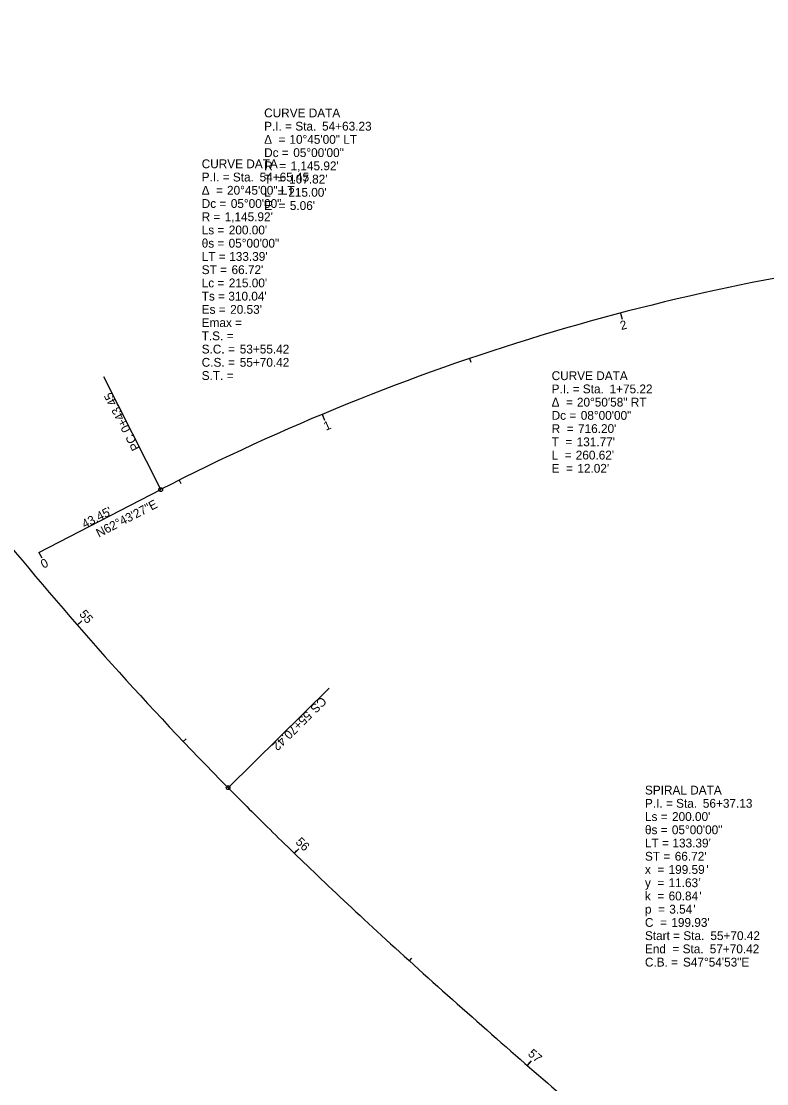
# Model space of a CAD drawing. Extents: x 1492452 to 1496782, y 514026 to 517659.
# Drawn here: x 1494542.5 to 1494779, y 514788.1 to 515125.3 of the extents above; entities that cross this region are included whole.
import ezdxf

# ---------------------------------------------------------------- set-up
doc = ezdxf.new("R2010")
doc.units = 0
for name, color, linetype in [('BR_X_SV_Abut', 7, 'Continuous'), ('Default', 7, 'Continuous'), ('DR_X_Ditch', 7, 'Continuous'), ('DR_X_Elev_Flow', 7, 'Continuous'), ('DT_X_Break_Line', 7, 'Continuous'), ('DT_X_Contour_Minor', 7, 'Continuous'), ('DT_X_Island', 7, 'Continuous'), ('DT_X_TIN_Hull', 7, 'Continuous'), ('DT_X_Triangles', 7, 'Continuous'), ('DT_X_Void', 7, 'Continuous'), ('GE_X_Cells', 7, 'Continuous'), ('PV_X_COP', 7, 'Continuous'), ('PV_X_EOP', 7, 'Continuous'), ('PV_X_Shoulder_Aggregate', 7, 'Continuous'), ('RD_X_Cells', 7, 'Continuous'), ('RD_X_GR_Lt', 7, 'Continuous'), ('RD_X_GR_Rt', 7, 'Continuous'), ('RD_X_Wall', 7, 'Continuous'), ('SN_X_Public', 7, 'Continuous'), ('SV_X_Random_Point', 7, 'Continuous'), ('SV_X_Top_of_Bank', 7, 'Continuous'), ('UT_X_Electric_Cells', 7, 'Continuous'), ('UT_X_Misc_Cells', 7, 'Continuous'), ('UT_X_Water', 7, 'Continuous'), ('UT_X_Water_Cells', 7, 'Continuous'), ('VG_X_Cells', 7, 'Continuous'), ('XS_X_Ground_Line', 7, 'Continuous')]:
    doc.layers.add(name, color=color, linetype=linetype)

msp = doc.modelspace()

# ---------------------------------------------------------------- linework, layer by layer
at = {"layer": 'Default'}
msp.add_line((1494548.11, 514956.7), (1494586.73, 514976.61), dxfattribs=at)
for centre, radius, start, end in [((1486425.91, 524780.42), 12277.67, 302.444021, 313.600151), ((1494914.94, 514340.04), 716.2, 96.42645, 117.27596)]:
    msp.add_arc(centre, radius, start, end, dxfattribs=at)
at = {"layer": 'DT_X_Contour_Minor'}
msp.add_line((1494560.25, 514933.64), (1494561.16, 514934.43), dxfattribs=at)
at = {"layer": 'DT_X_TIN_Hull'}
for p, q in [((1494732.57, 515032.63), (1494733.08, 515030.7)), ((1494684.7, 515018.23), (1494685.09, 515017.09)), ((1494637.96, 515000.51), (1494638.73, 514998.67)), ((1494592.56, 514979.58), (1494593.1, 514978.51)), ((1494548.11, 514956.7), (1494549.02, 514954.92))]:
    msp.add_line(p, q, dxfattribs=at)
at = {"layer": 'DT_X_Void'}
msp.add_line((1494586.73, 514976.61), (1494568.72, 515012.45), dxfattribs=at)
msp.add_circle((1494586.73, 514976.61), 0.6, dxfattribs=at)
at = {"layer": 'GE_X_Cells'}
msp.add_line((1494548.11, 514956.7), (1494586.73, 514976.61), dxfattribs=at)
for centre, radius, start, end in [((1486425.91, 524780.42), 12277.67, 302.444021, 313.600151), ((1494914.94, 514340.04), 716.2, 96.42645, 117.27596)]:
    msp.add_arc(centre, radius, start, end, dxfattribs=at)
at = {"layer": 'PV_X_EOP'}
msp.add_line((1494608.11, 514882), (1494640.16, 514913.59), dxfattribs=at)
msp.add_circle((1494608.11, 514882), 0.6, dxfattribs=at)
at = {"layer": 'PV_X_Shoulder_Aggregate'}
for p, q in [((1494560.25, 514933.64), (1494561.76, 514934.96)), ((1494593.91, 514896.67), (1494594.78, 514897.5)), ((1494629.13, 514861.19), (1494630.52, 514862.62)), ((1494665.64, 514827.03), (1494666.45, 514827.92)), ((1494703.04, 514793.85), (1494704.36, 514795.36))]:
    msp.add_line(p, q, dxfattribs=at)
at = {"layer": 'RD_X_Cells'}
msp.add_line((1494586.73, 514976.61), (1494568.72, 515012.45), dxfattribs=at)
msp.add_circle((1494586.73, 514976.61), 0.6, dxfattribs=at)
at = {"layer": 'RD_X_GR_Rt'}
msp.add_line((1494608.11, 514882), (1494640.16, 514913.59), dxfattribs=at)
msp.add_circle((1494608.11, 514882), 0.6, dxfattribs=at)
at = {"layer": 'RD_X_Wall'}
for p, q in [((1494560.25, 514933.64), (1494561.76, 514934.96)), ((1494629.13, 514861.19), (1494629.97, 514862.05)), ((1494703.04, 514793.85), (1494703.83, 514794.75))]:
    msp.add_line(p, q, dxfattribs=at)
at = {"layer": 'SV_X_Top_of_Bank'}
msp.add_arc((1495424.3, 515686.35), 1145.92, 213.83122, 224.58118, dxfattribs=at)
msp.add_arc((1495424.3, 515686.35), 1145.92, 213.83122, 224.58118, dxfattribs=at)
msp.add_open_spline([(1494608.11, 514882), (1494612.01, 514878.04), (1494619.86, 514870.19), (1494635.79, 514854.68), (1494656.04, 514835.67), (1494680.78, 514813.33), (1494705.84, 514791.35), (1494726.9, 514773.23), (1494743.8, 514758.81), (1494752.26, 514751.6), (1494756.49, 514748)], degree=3, dxfattribs=at)
msp.add_open_spline([(1494608.11, 514882), (1494612.01, 514878.04), (1494619.86, 514870.19), (1494635.79, 514854.68), (1494656.04, 514835.67), (1494680.78, 514813.33), (1494705.84, 514791.35), (1494726.9, 514773.23), (1494743.8, 514758.81), (1494752.26, 514751.6), (1494756.49, 514748)], degree=3, dxfattribs=at)
at = {"layer": 'UT_X_Misc_Cells'}
msp.add_line((1494586.73, 514976.61), (1494568.72, 515012.45), dxfattribs=at)
msp.add_circle((1494586.73, 514976.61), 0.6, dxfattribs=at)
at = {"layer": 'UT_X_Water_Cells'}
for p, q in [((1494732.57, 515032.63), (1494732.88, 515031.47)), ((1494637.96, 515000.51), (1494638.42, 514999.41)), ((1494548.11, 514956.7), (1494549.02, 514954.92))]:
    msp.add_line(p, q, dxfattribs=at)
at = {"layer": 'VG_X_Cells'}
msp.add_line((1494548.11, 514956.7), (1494549.02, 514954.92), dxfattribs=at)
at = {"layer": 'XS_X_Ground_Line'}
msp.add_line((1494608.11, 514882), (1494640.16, 514913.59), dxfattribs=at)
msp.add_circle((1494608.11, 514882), 0.6, dxfattribs=at)

# ---------------------------------------------------------------- texts
at = {"layer": 'BR_X_SV_Abut'}
for s, p in [('CURVE DATA', (1494619.55, 515094.76)), ('P.I. = Sta. ', (1494619.55, 515090.56)), ('54+63.23', (1494637.92, 515090.56)), ('Δ  = ', (1494619.55, 515086.36)), ('10°45\'00" LT', (1494627.57, 515086.36)), ('Dc = ', (1494619.55, 515082.16)), ('05°00\'00"', (1494628.79, 515082.16)), ('CURVE DATA', (1494599.74, 515078.61)), ('R  = ', (1494619.55, 515077.96)), ("1,145.92'", (1494627.92, 515077.96)), ('P.I. = Sta. ', (1494599.74, 515074.41)), ('54+65.45', (1494618.11, 515074.41)), ('T  = ', (1494619.55, 515073.76)), ("107.82'", (1494627.48, 515073.76)), ('Δ  = ', (1494599.74, 515070.21)), ('20°45\'00" LT', (1494607.77, 515070.21)), ('L  = ', (1494619.55, 515069.56)), ("215.00'", (1494627.2, 515069.56)), ('Dc = ', (1494599.74, 515066.01)), ('05°00\'00"', (1494608.98, 515066.01)), ('E  = ', (1494619.55, 515065.36)), ("5.06'", (1494627.7, 515065.36)), ('R = ', (1494599.74, 515061.81)), ("1,145.92'", (1494607.02, 515061.81)), ('Ls = ', (1494599.74, 515057.61)), ("200.00'", (1494608.33, 515057.61)), ('θs = ', (1494599.74, 515053.41)), ('05°00\'00"', (1494608.28, 515053.41)), ('LT = ', (1494599.74, 515049.21)), ("133.39'", (1494608.47, 515049.21)), ('ST = ', (1494599.74, 515045.01)), ("66.72'", (1494609.2, 515045.01)), ('Lc = ', (1494599.74, 515040.81)), ("215.00'", (1494608.33, 515040.81)), ('Ts = ', (1494599.74, 515036.61)), ("310.04'", (1494608.19, 515036.61)), ('Es = ', (1494599.74, 515032.41)), ("20.53'", (1494608.77, 515032.41)), ('Emax = ', (1494599.74, 515028.21)), ('T.S. = ', (1494599.74, 515024.01)), ('S.C. = ', (1494599.74, 515019.81)), ('53+55.42', (1494611.81, 515019.81)), ('C.S. = ', (1494599.74, 515015.61)), ('55+70.42', (1494611.81, 515015.61)), ('S.T. = ', (1494599.74, 515011.41)), ('SPIRAL DATA', (1494740.35, 514879.85)), ('P.I. = Sta. ', (1494740.35, 514875.65)), ('56+37.13', (1494758.72, 514875.65)), ('Ls = ', (1494740.35, 514871.45)), ("200.00'", (1494748.94, 514871.45)), ('θs = ', (1494740.35, 514867.25)), ('05°00\'00"', (1494748.89, 514867.25)), ('LT = ', (1494740.35, 514863.05)), ("133.39'", (1494749.08, 514863.05)), ('ST = ', (1494740.35, 514858.85)), ("66.72'", (1494749.81, 514858.85)), ('199.59', (1494747.85, 514854.65)), ("'", (1494759.81, 514854.65)), ('x  = ', (1494740.35, 514854.65)), ('y  = ', (1494740.35, 514850.45)), ('11.63', (1494747.85, 514850.45)), ("'", (1494757.35, 514850.45)), ('k  = ', (1494740.35, 514846.25)), ('60.84', (1494747.85, 514846.25)), ("'", (1494757.64, 514846.25)), ('p  = ', (1494740.35, 514842.05)), ('3.54', (1494748.07, 514842.05)), ("'", (1494755.68, 514842.05)), ('C  = ', (1494740.35, 514837.85)), ("199.93'", (1494748.72, 514837.85)), ('Start = Sta. ', (1494740.35, 514833.65)), ('55+70.42', (1494761.11, 514833.65)), ('End  = Sta. ', (1494740.35, 514829.45)), ('57+70.42', (1494760.9, 514829.45)), ('C.B. = ', (1494740.35, 514825.25)), ('S47°54\'53"E', (1494752.42, 514825.25))]:
    msp.add_text(s, height=2.8, dxfattribs=at).set_placement(p)
at = {"layer": 'DR_X_Ditch'}
msp.add_text("43.45'", height=2.8, rotation=27.276, dxfattribs=at).set_placement((1494562.6, 514964.22))
at = {"layer": 'DR_X_Elev_Flow'}
for s, p in [('CURVE DATA', (1494710.75, 515011.37)), ('P.I. = Sta. ', (1494710.75, 515007.17)), ('1+75.22', (1494729.12, 515007.17)), ('Δ  = ', (1494710.75, 515002.97)), ('20°50\'58" RT', (1494718.77, 515002.97)), ('Dc = ', (1494710.75, 514998.77)), ('08°00\'00"', (1494719.99, 514998.77)), ('R  = ', (1494710.75, 514994.57)), ("716.20'", (1494719.12, 514994.57)), ('T  = ', (1494710.75, 514990.37)), ("131.77'", (1494718.69, 514990.37)), ('L  = ', (1494710.75, 514986.17)), ("260.62'", (1494718.4, 514986.17)), ('E  = ', (1494710.75, 514981.97)), ("12.02'", (1494718.91, 514981.97))]:
    msp.add_text(s, height=2.8, dxfattribs=at).set_placement(p)
at = {"layer": 'DT_X_Break_Line'}
msp.add_text('N62°43\'27"E', height=2.8, rotation=27.276, dxfattribs=at).set_placement((1494567.12, 514961.35))
at = {"layer": 'DT_X_Island'}
for s, p in [('CURVE DATA', (1494710.75, 515011.37)), ('P.I. = Sta. ', (1494710.75, 515007.17)), ('1+75.22', (1494729.12, 515007.17)), ('Δ  = ', (1494710.75, 515002.97)), ('20°50\'58" RT', (1494718.77, 515002.97)), ('Dc = ', (1494710.75, 514998.77)), ('08°00\'00"', (1494719.99, 514998.77)), ('R  = ', (1494710.75, 514994.57)), ("716.20'", (1494719.12, 514994.57)), ('T  = ', (1494710.75, 514990.37)), ("131.77'", (1494718.69, 514990.37)), ('L  = ', (1494710.75, 514986.17)), ("260.62'", (1494718.4, 514986.17)), ('E  = ', (1494710.75, 514981.97)), ("12.02'", (1494718.91, 514981.97))]:
    msp.add_text(s, height=2.8, dxfattribs=at).set_placement(p)
at = {"layer": 'DT_X_TIN_Hull'}
for s, rotation, p in [('2', 14.752, (1494732.86, 515027.23)), ('1', 22.752, (1494639.14, 514995.26)), ('0', 27.276, (1494549.55, 514951.48))]:
    msp.add_text(s, height=2.8, rotation=rotation, dxfattribs=at).set_placement(p)
at = {"layer": 'DT_X_Triangles'}
for s, p in [('CURVE DATA', (1494619.55, 515094.76)), ('P.I. = Sta. ', (1494619.55, 515090.56)), ('54+63.23', (1494637.92, 515090.56)), ('Δ  = ', (1494619.55, 515086.36)), ('10°45\'00" LT', (1494627.57, 515086.36)), ('Dc = ', (1494619.55, 515082.16)), ('05°00\'00"', (1494628.79, 515082.16)), ('CURVE DATA', (1494599.74, 515078.61)), ('R  = ', (1494619.55, 515077.96)), ("1,145.92'", (1494627.92, 515077.96)), ('P.I. = Sta. ', (1494599.74, 515074.41)), ('54+65.45', (1494618.11, 515074.41)), ('T  = ', (1494619.55, 515073.76)), ("107.82'", (1494627.48, 515073.76)), ('Δ  = ', (1494599.74, 515070.21)), ('20°45\'00" LT', (1494607.77, 515070.21)), ('L  = ', (1494619.55, 515069.56)), ("215.00'", (1494627.2, 515069.56)), ('Dc = ', (1494599.74, 515066.01)), ('05°00\'00"', (1494608.98, 515066.01)), ('E  = ', (1494619.55, 515065.36)), ("5.06'", (1494627.7, 515065.36)), ('R = ', (1494599.74, 515061.81)), ("1,145.92'", (1494607.02, 515061.81)), ('Ls = ', (1494599.74, 515057.61)), ("200.00'", (1494608.33, 515057.61)), ('θs = ', (1494599.74, 515053.41)), ('05°00\'00"', (1494608.28, 515053.41)), ('LT = ', (1494599.74, 515049.21)), ("133.39'", (1494608.47, 515049.21)), ('ST = ', (1494599.74, 515045.01)), ("66.72'", (1494609.2, 515045.01)), ('Lc = ', (1494599.74, 515040.81)), ("215.00'", (1494608.33, 515040.81)), ('Ts = ', (1494599.74, 515036.61)), ("310.04'", (1494608.19, 515036.61)), ('Es = ', (1494599.74, 515032.41)), ("20.53'", (1494608.77, 515032.41)), ('Emax = ', (1494599.74, 515028.21)), ('T.S. = ', (1494599.74, 515024.01)), ('S.C. = ', (1494599.74, 515019.81)), ('53+55.42', (1494611.81, 515019.81)), ('C.S. = ', (1494599.74, 515015.61)), ('55+70.42', (1494611.81, 515015.61)), ('S.T. = ', (1494599.74, 515011.41)), ('SPIRAL DATA', (1494740.35, 514879.85)), ('P.I. = Sta. ', (1494740.35, 514875.65)), ('56+37.13', (1494758.72, 514875.65)), ('Ls = ', (1494740.35, 514871.45)), ("200.00'", (1494748.94, 514871.45)), ('θs = ', (1494740.35, 514867.25)), ('05°00\'00"', (1494748.89, 514867.25)), ('LT = ', (1494740.35, 514863.05)), ("133.39'", (1494749.08, 514863.05)), ('ST = ', (1494740.35, 514858.85)), ("66.72'", (1494749.81, 514858.85)), ('199.59', (1494747.85, 514854.65)), ("'", (1494759.81, 514854.65)), ('x  = ', (1494740.35, 514854.65)), ('y  = ', (1494740.35, 514850.45)), ('11.63', (1494747.85, 514850.45)), ("'", (1494757.35, 514850.45)), ('k  = ', (1494740.35, 514846.25)), ('60.84', (1494747.85, 514846.25)), ("'", (1494757.64, 514846.25)), ('p  = ', (1494740.35, 514842.05)), ('3.54', (1494748.07, 514842.05)), ("'", (1494755.68, 514842.05)), ('C  = ', (1494740.35, 514837.85)), ("199.93'", (1494748.72, 514837.85)), ('Start = Sta. ', (1494740.35, 514833.65)), ('55+70.42', (1494761.11, 514833.65)), ('End  = Sta. ', (1494740.35, 514829.45)), ('57+70.42', (1494760.9, 514829.45)), ('C.B. = ', (1494740.35, 514825.25)), ('S47°54\'53"E', (1494752.42, 514825.25))]:
    msp.add_text(s, height=2.8, dxfattribs=at).set_placement(p)
at = {"layer": 'DT_X_Void'}
for s, p in [('0+43.45', (1494577.34, 514995.64)), ('PC', (1494580.32, 514989.84))]:
    msp.add_text(s, height=2.8, rotation=117.276, dxfattribs=at).set_placement(p)
at = {"layer": 'PV_X_COP'}
for s, p in [('CURVE DATA', (1494619.55, 515094.76)), ('P.I. = Sta. ', (1494619.55, 515090.56)), ('54+63.23', (1494637.92, 515090.56)), ('Δ  = ', (1494619.55, 515086.36)), ('10°45\'00" LT', (1494627.57, 515086.36)), ('Dc = ', (1494619.55, 515082.16)), ('05°00\'00"', (1494628.79, 515082.16)), ('CURVE DATA', (1494599.74, 515078.61)), ('R  = ', (1494619.55, 515077.96)), ("1,145.92'", (1494627.92, 515077.96)), ('P.I. = Sta. ', (1494599.74, 515074.41)), ('54+65.45', (1494618.11, 515074.41)), ('T  = ', (1494619.55, 515073.76)), ("107.82'", (1494627.48, 515073.76)), ('Δ  = ', (1494599.74, 515070.21)), ('20°45\'00" LT', (1494607.77, 515070.21)), ('L  = ', (1494619.55, 515069.56)), ("215.00'", (1494627.2, 515069.56)), ('Dc = ', (1494599.74, 515066.01)), ('05°00\'00"', (1494608.98, 515066.01)), ('E  = ', (1494619.55, 515065.36)), ("5.06'", (1494627.7, 515065.36)), ('R = ', (1494599.74, 515061.81)), ("1,145.92'", (1494607.02, 515061.81)), ('Ls = ', (1494599.74, 515057.61)), ("200.00'", (1494608.33, 515057.61)), ('θs = ', (1494599.74, 515053.41)), ('05°00\'00"', (1494608.28, 515053.41)), ('LT = ', (1494599.74, 515049.21)), ("133.39'", (1494608.47, 515049.21)), ('ST = ', (1494599.74, 515045.01)), ("66.72'", (1494609.2, 515045.01)), ('Lc = ', (1494599.74, 515040.81)), ("215.00'", (1494608.33, 515040.81)), ('Ts = ', (1494599.74, 515036.61)), ("310.04'", (1494608.19, 515036.61)), ('Es = ', (1494599.74, 515032.41)), ("20.53'", (1494608.77, 515032.41)), ('Emax = ', (1494599.74, 515028.21)), ('T.S. = ', (1494599.74, 515024.01)), ('S.C. = ', (1494599.74, 515019.81)), ('53+55.42', (1494611.81, 515019.81)), ('C.S. = ', (1494599.74, 515015.61)), ('55+70.42', (1494611.81, 515015.61)), ('S.T. = ', (1494599.74, 515011.41)), ('SPIRAL DATA', (1494740.35, 514879.85)), ('P.I. = Sta. ', (1494740.35, 514875.65)), ('56+37.13', (1494758.72, 514875.65)), ('Ls = ', (1494740.35, 514871.45)), ("200.00'", (1494748.94, 514871.45)), ('θs = ', (1494740.35, 514867.25)), ('05°00\'00"', (1494748.89, 514867.25)), ('LT = ', (1494740.35, 514863.05)), ("133.39'", (1494749.08, 514863.05)), ('ST = ', (1494740.35, 514858.85)), ("66.72'", (1494749.81, 514858.85)), ('199.59', (1494747.85, 514854.65)), ("'", (1494759.81, 514854.65)), ('x  = ', (1494740.35, 514854.65)), ('y  = ', (1494740.35, 514850.45)), ('11.63', (1494747.85, 514850.45)), ("'", (1494757.35, 514850.45)), ('k  = ', (1494740.35, 514846.25)), ('60.84', (1494747.85, 514846.25)), ("'", (1494757.64, 514846.25)), ('p  = ', (1494740.35, 514842.05)), ('3.54', (1494748.07, 514842.05)), ("'", (1494755.68, 514842.05)), ('C  = ', (1494740.35, 514837.85)), ("199.93'", (1494748.72, 514837.85)), ('Start = Sta. ', (1494740.35, 514833.65)), ('55+70.42', (1494761.11, 514833.65)), ('End  = Sta. ', (1494740.35, 514829.45)), ('57+70.42', (1494760.9, 514829.45)), ('C.B. = ', (1494740.35, 514825.25)), ('S47°54\'53"E', (1494752.42, 514825.25))]:
    msp.add_text(s, height=2.8, dxfattribs=at).set_placement(p)
at = {"layer": 'PV_X_EOP'}
for s, p in [('CS', (1494637.69, 514911.09)), ('55+70.42', (1494633.04, 514906.51))]:
    msp.add_text(s, height=2.8, rotation=224.5812, dxfattribs=at).set_placement(p)
at = {"layer": 'PV_X_Shoulder_Aggregate'}
for s, rotation, p in [('55', 311.0604, (1494560.73, 514936.98)), ('56', 315.951, (1494629.32, 514864.54)), ('57', 318.9614, (1494703.02, 514797.25))]:
    msp.add_text(s, height=2.8, rotation=rotation, dxfattribs=at).set_placement(p)
at = {"layer": 'RD_X_Cells'}
for s, p in [('0+43.45', (1494577.34, 514995.64)), ('PC', (1494580.32, 514989.84))]:
    msp.add_text(s, height=2.8, rotation=117.276, dxfattribs=at).set_placement(p)
at = {"layer": 'RD_X_GR_Lt'}
msp.add_text("43.45'", height=2.8, rotation=27.276, dxfattribs=at).set_placement((1494562.6, 514964.22))
at = {"layer": 'RD_X_GR_Rt'}
for s, p in [('CS', (1494637.69, 514911.09)), ('55+70.42', (1494633.04, 514906.51))]:
    msp.add_text(s, height=2.8, rotation=224.5812, dxfattribs=at).set_placement(p)
at = {"layer": 'RD_X_Wall'}
msp.add_text('55', height=2.8, rotation=311.0604, dxfattribs=at).set_placement((1494560.73, 514936.98))
at = {"layer": 'SN_X_Public'}
for s, p in [('CURVE DATA', (1494710.75, 515011.37)), ('P.I. = Sta. ', (1494710.75, 515007.17)), ('1+75.22', (1494729.12, 515007.17)), ('Δ  = ', (1494710.75, 515002.97)), ('20°50\'58" RT', (1494718.77, 515002.97)), ('Dc = ', (1494710.75, 514998.77)), ('08°00\'00"', (1494719.99, 514998.77)), ('R  = ', (1494710.75, 514994.57)), ("716.20'", (1494719.12, 514994.57)), ('T  = ', (1494710.75, 514990.37)), ("131.77'", (1494718.69, 514990.37)), ('L  = ', (1494710.75, 514986.17)), ("260.62'", (1494718.4, 514986.17)), ('E  = ', (1494710.75, 514981.97)), ("12.02'", (1494718.91, 514981.97))]:
    msp.add_text(s, height=2.8, dxfattribs=at).set_placement(p)
at = {"layer": 'SV_X_Random_Point'}
msp.add_text('N62°43\'27"E', height=2.8, rotation=27.276, dxfattribs=at).set_placement((1494567.12, 514961.35))
at = {"layer": 'UT_X_Electric_Cells'}
msp.add_text('N62°43\'27"E', height=2.8, rotation=27.276, dxfattribs=at).set_placement((1494567.12, 514961.35))
at = {"layer": 'UT_X_Misc_Cells'}
for s, p in [('0+43.45', (1494577.34, 514995.64)), ('PC', (1494580.32, 514989.84))]:
    msp.add_text(s, height=2.8, rotation=117.276, dxfattribs=at).set_placement(p)
at = {"layer": 'UT_X_Water'}
msp.add_text("43.45'", height=2.8, rotation=27.276, dxfattribs=at).set_placement((1494562.6, 514964.22))
at = {"layer": 'UT_X_Water_Cells'}
msp.add_text('0', height=2.8, rotation=27.276, dxfattribs=at).set_placement((1494549.55, 514951.48))
at = {"layer": 'VG_X_Cells'}
msp.add_text('0', height=2.8, rotation=27.276, dxfattribs=at).set_placement((1494549.55, 514951.48))
at = {"layer": 'XS_X_Ground_Line'}
for s, p in [('CS', (1494637.69, 514911.09)), ('55+70.42', (1494633.04, 514906.51))]:
    msp.add_text(s, height=2.8, rotation=224.5812, dxfattribs=at).set_placement(p)

doc.saveas('drawing.dxf')
